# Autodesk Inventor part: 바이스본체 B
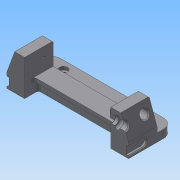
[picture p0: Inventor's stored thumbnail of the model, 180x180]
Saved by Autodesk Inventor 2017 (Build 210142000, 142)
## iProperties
Created: 2017-04
Part Number: 바이스본체 B
Material: 알루미늄 6061
Document SubType Name: Modeling
Designer: mduedu
Density: 2.71 g/cm^3
Mass: 324.113 g
Surface Area: 275.971 cm^2
Volume: 119.599 cm^3
Appearance: 기본값
Author: mduedu
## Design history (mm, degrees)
sketch "스케치1"
  geometry: L1 (-75, 0)-(75, 0); L2 (-75, 0)-(-75, 17); L3 (-53, 17)-(53, 17); L4 (75, 17)-(75, 0); L5 (-75, 17)-(-65.173, 44); L6 (-65.173, 44)-(-53, 44); L7 (-53, 44)-(-53, 17); L8 (0, 0)-(0, 17); L9 (75, 17)-(65.173, 44); L10 (65.173, 44)-(53, 44); L11 (53, 44)-(53, 17); 1 further point
  constraints: 22 end point, 4 perpendicular, 2 horizontal alignment, 2 midpoint, 2 symmetric about line, 1 coincident, 1 collinear, 1 horizontal, 1 vertical
  dimensions: "d0" = 150 distance of L1.start L1.end; "d1" = 17 distance of L1.start L2.end; "d2" = 27 distance of L3.start L6.end; "d3" = 22 distance of L3.start L2.end; "d4" = 70 deg angle of L3 L5; "d54" = 20 deg angle of L9 L4
extrude "돌출1" new body sketch "스케치1" stored distance "d5" = 70; taper "d6" = 0 deg
sketch "스케치2"
  geometry: L1 (0, 70)-(106, 70) reference; L2 (106, 70)-(106, 0) reference; L3 (106, 0)-(0, 0) reference; L4 (0, 47)-(106, 47); L5 (106, 47)-(106, 23); L6 (106, 23)-(0, 23); L7 (0, 23)-(0, 47); L8 (0, 70)-(0, 0) reference; 2 further points
  constraints: 8 end point, 2 parallel, 2 point on line, 1 horizontal, 1 horizontal alignment, 1 midpoint, 1 perpendicular
  dimensions: "d7" = 24 distance between parallel lines of L6 L4
extrude "돌출2" cut sketch "스케치2" stored distance "d9" = 70; taper "d10" = 0 deg
sketch "스케치3"
  geometry: L1 (22, -23)-(128, -23) reference; L2 (128, -47)-(22, -47) reference; L3 (22, -18)-(128, -18); L4 (128, -52)-(22, -52); L5 (22, -18)-(22, -52); L6 (128, -18)-(128, -52); 1 further point
  constraints: 8 end point, 3 parallel, 2 point on line, 1 perpendicular
  dimensions: "d11" = 5 distance between parallel lines of L3 L1; "d12" = 5 distance between parallel lines of L4 L2
extrude "돌출3" cut sketch "스케치3" distance "d13" = 12; taper "d14" = 0 deg
fillet "모깎기1" dims "d15" = 3, "d16" = 3
sketch "스케치4"
  geometry: L1 (103, 23)-(3, 23) reference; L2 (0, 26)-(0, 0) reference; L3 (106, 0)-(0, 0) reference; L4 (106, 26)-(106, 0) reference; L5 (96, 0)-(90, 0); L6 (90, 0)-(90, 19.5); L7 (96, 19.5)-(96, 0); L8 (90, 19.5)-(96, 19.5); A1 r 3 centre (3, 26) between (0, 26) and (3, 23) reference; A2 r 3 centre (103, 26) between (103, 23) and (106, 26) reference; 1 further point
  constraints: 8 end point, 2 perpendicular, 1 horizontal, 1 parallel, 1 point on line
  dimensions: "d17" = 10 distance between parallel lines of L7 L4; "d18" = 6 distance between parallel lines of L7 L6; "d27" = 3.5 distance between parallel lines of L8 L1
extrude "돌출4" join sketch "스케치4" distance "d19" = 12; taper "d20" = 0 deg
chamfer "모따기1" distance "d21" = 3; stored, may be unused: second distance "d22" = 2, angle "d23" = 45 deg
chamfer "모따기2" distance "d24" = 3; stored, may be unused: second distance "d25" = 2, angle "d26" = 45 deg
sketch "스케치5"
  geometry: L1 (-15.5, 35.8)-(-15.5, -25.8) reference; L2 (19.5, 0)-(0, 0) reference; C1 r 6.5 at (9.5, 15); 1 further point
  constraints: 1 centre point
  dimensions: "d28" = 13 diameter of C1; "d30" = 15 distance from line of C1.centre L2; "d31" = 25 distance from line of C1.centre L1
extrude "돌출5" cut sketch "스케치5" stored distance "d32" = 12; taper "d33" = 0 deg
sketch "스케치6"
  geometry: C1 r 5 at (-10, 15); C2 r 5 at (-60, 15); A1 r 6.5 centre (-10, 15) between (-15.766, 12) and (-4.234, 12) reference; A2 r 6.5 centre (-60, 15) between (-65.766, 12) and (-54.234, 12) reference; 1 further point
  constraints: 2 centre point, 2 coincident
  dimensions: "d34" = 10 diameter of C1; "d35" = 10 diameter of C2 (= d34)
extrude "돌출6" cut sketch "스케치6" stored distance "d36" = 12; taper "d37" = 0 deg
chamfer "모따기3" distance "d38" = 1; stored, may be unused: second distance "d39" = 2, angle "d40" = 45 deg
chamfer "모따기4" distance "d41" = 1; stored, may be unused: second distance "d42" = 2, angle "d43" = 45 deg
sketch "스케치7"
  geometry: L1 (-35, 35.8)-(-35, -25.8) reference; L2 (-70, 0)-(0, 0) reference; C1 r 5 at (-35, 15); 1 further point
  constraints: 1 centre point, 1 point on line
  dimensions: "d44" = 10 diameter of C1; "d45" = 15 distance from line of C1.centre L2
extrude "돌출7" cut sketch "스케치7" stored distance "d46" = 12; taper "d47" = 0 deg
chamfer "모따기5" distance "d48" = 1; stored, may be unused: second distance "d49" = 2, angle "d50" = 45 deg
node "작업축1"
sketch "스케치8"
  geometry: L1 (-105, 32)-(105, 32) reference; L2 (58, 32)-(64, 32); L3 (64, 32)-(64, 40); L4 (64, 40)-(58, 40); L5 (58, 40)-(58, 32); L6 (53, 38)-(53, 26) reference; 1 further point
  constraints: 8 end point, 2 parallel, 1 horizontal, 1 perpendicular, 1 point on line
  dimensions: "d51" = 5 distance from line of L6 L2.start; "d52" = 6 distance of L3.end L4.end; "d53" = 16 diameter of L4 L1
revolve "회전1" sketch "스케치8" stored, may be unused: angle "d55" = 90 deg
fillet "모깎기2"
chamfer "모따기6" distance "d56" = 1; stored, may be unused: second distance "d57" = 2, angle "d58" = 45 deg
sketch "스케치9"
  geometry: L1 (17.5, 3)-(52.5, 3); L2 (52.5, 13)-(17.5, 13); L3 (70, 0)-(0, 0) reference; L4 (17.5, 8)-(52.5, 8); A1 r 5 centre (17.5, 8) between (17.5, 13) and (17.5, 3); A2 r 5 centre (52.5, 8) between (52.5, 3) and (52.5, 13); 3 further points
  constraints: 6 end point, 4 point on circle, 3 tangent, 2 centre point, 2 midpoint, 2 parallel, 1 horizontal, 1 vertical alignment
  dimensions: "d59" = 35 distance of L4.start L4.end; "d61" = 5 radius of A2; "d62" = 8 distance between parallel lines of L3 L4
extrude "돌출8" cut sketch "스케치9" distance "d63" = 3; taper "d64" = 0 deg
chamfer "모따기7" distance "d65" = 1; stored, may be unused: second distance "d66" = 2, angle "d67" = 45 deg
chamfer "모따기8" distance "d68" = 1; stored, may be unused: second distance "d69" = 2, angle "d70" = 45 deg
feature "분할1"
sketch "스케치10"
  geometry: A1 r 5 centre (0, 0) between (0, 5) and (0, -5) reference; 1 further point
  constraints: 1 coincident
hole "구멍1" sketch "스케치10" at (0, 0) diameter "d71" = 2.459; stored, may be unused: countersink angle "d75" = 90 deg, drill point angle "d77" = 120 deg; dims "d72" = 4.5, "d73" = 4, "d74" = 2, "d76" = 6
sketch "스케치11"
  geometry: L1 (0, 0)-(0, 27) reference; L2 (0, 27)-(-35, 27) reference; 2 further points
  dimensions: "d78" = 12 distance from line of point (-12, 15.5) L1; "d79" = 11.5 distance from line of point (-12, 15.5) L2
hole "구멍2" sketch "스케치11" at (-12, 15.5) diameter "d80" = 3.242; stored, may be unused: countersink angle "d84" = 90 deg, drill point angle "d86" = 120 deg; dims "d81" = 8, "d82" = 4, "d83" = 2, "d85" = 10
sketch "스케치12"
  geometry: L1 (-75, -35)-(-75, 0) reference; L2 (75, -35)-(75, 0) reference; L3 (75, -35)-(-75, -35); L4 (-75, -35)-(-75, -55); L5 (-75, -55)-(75, -55); L6 (75, -55)-(75, -35); 1 further point
  constraints: 8 end point, 2 parallel, 1 horizontal, 1 perpendicular, 1 point on line
  dimensions: "d87" = 20 distance of L3.end L4.end; "d89" = 150 distance of L4.end L5.end (derived)
extrude "돌출9" join sketch "스케치12" distance "d90" = 10; taper "d91" = 0 deg
sketch "스케치13"
  geometry: L1 (-75, 55)-(-75, 35) reference; L2 (75, 35)-(75, 55) reference; L3 (-75, 45)-(75, 45); 3 further points
  constraints: 2 end point, 2 midpoint, 2 point on line
  dimensions: "d92" = 50 horizontal distance of point (-50, 45) point (0, 0); "d93" = 100 distance of point (50, 45) point (-50, 45)
fillet "모깎기3" dims "d94" = 12
chamfer "모따기9" distance "d95" = 1; stored, may be unused: second distance "d96" = 2, angle "d97" = 45 deg
hole "구멍3" sketch "스케치13" diameter "d98" = 4.134; stored, may be unused: countersink angle "d102" = 90 deg, drill point angle "d104" = 118 deg; dims "d99" = 6, "d100" = 10, "d101" = 4, "d103" = 8
node "솔리드1"
mirror "대칭1"
mirror "대칭2"
mirror "대칭3"
mirror "대칭4"
node "투영된 루프1"
